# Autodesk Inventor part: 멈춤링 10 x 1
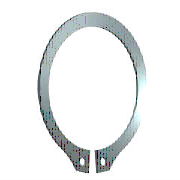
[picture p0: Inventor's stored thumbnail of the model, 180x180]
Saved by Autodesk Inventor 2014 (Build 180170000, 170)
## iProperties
IsCustomPart: 0
Created: 2009-02
Part Number: 멈춤링 10 x 1
Material: Steel, Mild
Description: 리테이닝 링(C형)
Document SubType Name: Modeling
Standard: KS B 1336
Designer: SeoGD™
Standards Organization: KS
Language: ko-KR
Size Designation: 10 x 1
Categories: <MemberInstance><Categories><Category DisplayName="샤프트 부품" InternalName="7f7aeb1f-a693-4053-b835-cee3144e0d98" Mnemonic="SHFT"><Category DisplayName="써클립" Inter
Density: 1 g/cm^3
Appearance: Metal-Steel
Author: SeoGD™
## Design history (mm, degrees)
sketch "스케치1"
  geometry: L1 (-6, 0)-(6, 0) reference; L2 (0, 20.189)-(0, -80.536) reference; L3 (-48.09, 0)-(48.09, 0) reference; L4 (-0.3, -9.791)-(-0.3, -12.791); L5 (-0.3, -6.54)-(-0.3, -13.29); L6 (-2.795, 1.6)-(3.672, 1.6); L7 (0.3, -6.54)-(0.3, -13.29); L8 (0.3, -9.791)-(0.3, -12.791); C1 r 0.6 at (-1.2, -11.486); C2 r 0.6 at (1.2, -11.486); A1 r 4.8 centre (0, -5) between (0.3, -9.791) and (-0.3, -9.791); A2 r 6.2 centre (0, -4.6) between (2.988, -10.033) and (-2.988, -10.033); A3 r 7.796 centre (0, -5) between (-1.418, -12.666) and (-0.3, -12.791); A4 r 1.2 centre (-1.2, -11.486) between (-2.383, -11.285) and (-1.418, -12.666); A5 r 1.2 centre (-3.566, -11.084) between (-2.383, -11.285) and (-2.988, -10.033); A6 r 1.2 centre (3.566, -11.084) between (2.988, -10.033) and (2.383, -11.285); A7 r 1.2 centre (1.2, -11.486) between (1.418, -12.666) and (2.383, -11.285); A8 r 7.796 centre (0, -5) between (0.3, -12.791) and (1.418, -12.666)
  constraints: 16 point on circle, 12 end point, 10 centre point, 9 symmetric about line, 5 point on line, 4 tangent, 3 coincident, 2 horizontal, 1 perpendicular, 1 vertical, 5 other
  dimensions: "d0" = 9.6 diameter of A1 (= ND); "d1" = 3 distance of L4.end L4.start (= SRB2); "d6" = 0.3 distance between parallel lines of L2 L5 (= 0.25 x SD5); "d7" = 1.6 distance between parallel lines of L6 L3 (= SRB1); "d8" = 0.4 distance of A1.centre A2.centre (= 0.25 x SRB1); "d9" = 1.2 radius of A4 (= SD5); "d10" = 1.2 radius of A5 (= SD5); "d11" = 0.9 distance from line of L4 A4.centre (= 0.75 x SD5); "d12" = 1.2 diameter of C1 (= SD5); "d13" = 1.2 diameter of C2 (= SD5); "d14" = 5 distance from line of A1.centre L1 (= 0.5 x WD)
extrude "본체" new body sketch "스케치1" distance "d2" = 1 (= SD); taper "d3" = 0 deg
workaxis "Work Axis1"
workplane "Work Plane1"
body "Solid1"
other parameters: "SD" = 1 [user parameter; used in 1 equation term], "SRB1" = 1.6 [user parameter; used in 2 equation terms], "ND" = 9.6 [user parameter; used in 1 equation term], "SRB2" = 3 [user parameter; used in 1 equation term], "SD5" = 1.2 [user parameter; used in 6 equation terms], "d15" = 0, "d16" = 0, "d17" = 0, "d41" = 0, "d42" = 0, "SD3" = 9.3 [user parameter], "WDMAX" = 11 [user parameter]
